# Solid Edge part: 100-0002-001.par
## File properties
Title: 100-0002-00.par
Author: rtconerl
Template: ANSIMM.PAR
Last saved by: jccrumbl
Revision: 46
Application: Solid Edge
Revision: A
Teamcenter Item Type: Item
Accuracy: 0.99
TC Engineering Description: Valve Stem
TC_ImportTime: 2008-07-08
PartType: -
Last Saved Version: -
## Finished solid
Body 1: solid body, 17 faces, 34 edges, 20 vertices.
  Faces by surface: plane 12, cylinder 3, cone 2
  Edges by curve: line 16, circle 14, intersection 4
Bounding box of the edges (mm): 20.000 x 20.000 x 107.000, from (-10, -10, 0) to (10, 10, 107).
Cylindrical faces by radius (mm): R7.5 x2, R10 x1
Conical faces (half-angle, radius in mm at the cone's reference point): 45 deg R7.5 x2
Planar faces by outward normal: +x 1, +y 1, +z 4, -x 1, -y 1, -z 4
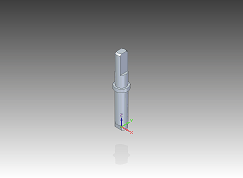
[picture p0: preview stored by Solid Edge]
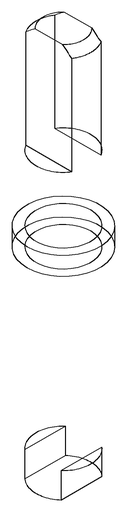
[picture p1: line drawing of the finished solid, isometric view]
